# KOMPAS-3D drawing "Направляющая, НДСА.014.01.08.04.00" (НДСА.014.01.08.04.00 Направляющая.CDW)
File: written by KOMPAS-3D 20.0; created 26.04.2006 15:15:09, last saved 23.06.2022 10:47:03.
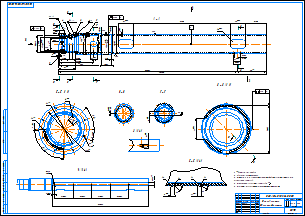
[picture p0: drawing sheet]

Sheet 1: A1, landscape

Document properties: Автор: Устинов А.В.; Организация: Эсто-вакуум; Полное имя файла: НДСА.014.01.08.04.00 Направляющая.a3d; 245497770678: <item xmlns="http://appius.ru/pdm" xmlns:xs="http://www.w3.org/2001/XMLSchema" xmlns:xsi="http://www.w3.org/2001/XMLSchema-instance" xsi:type="item">  <element xmlns:d2p1="http://v8.1c.ru/8.1/data/enterprise/current-config" xsi:type="d2p1:CatalogRef.aps_Элемен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; PLM_CDWXDTO: <item xmlns="http://appius.ru/pdm" xmlns:xs="http://www.w3.org/2001/XMLSchema" xmlns:xsi="http://www.w3.org/2001/XMLSchema-instance" xsi:type="item">  <element xmlns:d2p1="http://v8.1c.ru/8.1/data/enterprise/current-config" xsi:type="d2p1:CatalogRef.aps_Элемен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; Масса: 36.6515

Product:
- Part/product: Направляющая  | designation НДСА.014.01.08.04.00
    Масса: 36.6515
  - Component [detail]: Труба  | designation НДСА.014.01.08.04.04  | Материал: Труба$d140х10 ГОСТ 8732-78;20 ГОСТ 8731-74$ (density 0 kg/m3); source file: НДСА.014.01.08.04.04 Труба.m3d
  - Component [detail]: Труба  | designation НДСА.014.01.08.04.02  | Материал: Труба$d114х8 ГОСТ 8732-78;20 ГОСТ 8731-74$ (density 0 kg/m3); source file: НДСА.014.01.08.04.02 Труба.m3d
  - Component [detail]: Втулка  | designation НДСА.014.01.08.04.01  | Материал: Сталь 20 ГОСТ 1050-88 (density 0 kg/m3); source file: НДСА.014.01.08.04.01 Втулка.m3d
  - Component [detail]: Втулка обр. (направл.)  | Материал: Сталь 20 ГОСТ 1050-88 (density 7859 kg/m3); Масса: 1.41117; source file: Втулка обр. (направл.).m3d
  - Component [detail]: Труба обр. (направл.)  | Материал: Труба$d114х8 ГОСТ 8732-78;20 ГОСТ 8731-74$ (density 7859 kg/m3); Масса: 1.17039; source file: Труба обр. (направл.).m3d
  - Component [detail]: Шов сварной 3 (гидроподъем.)  | qty 2  | Масса: 0.0486432; source file: Шов сварной 3 (гидроподъем.).m3d
  - Component [detail]: Втулка  | designation НДСА.014.01.08.04.03  | Материал: Сталь 20 ГОСТ 1050-88 (density 7859 kg/m3); Масса: 0.959708; source file: НДСА.014.01.08.04.03 Втулка.m3d
  - Component [detail]: Труба обр. 2 (направл.)  | Материал: Труба$d140х10 ГОСТ 8732-78;20 ГОСТ 8731-74$ (density 7859 kg/m3); Масса: 32.9315; source file: Труба обр. 2 (направл.).m3d
  - Component [detail]: Шов сварной 4 (гидроподъем.)  | Масса: 0.0814568; source file: Шов сварной 4 (гидроподъем.).m3d

Title block, sheet 1: Наименование: Направляющая / Сборочный чертеж; Масса: 36,65; scale: 1:2,5; Количество листов документа: 1; organisation: ЭСТО; Форматы листов документа: A1; stored path: D:\WorkPDM\Устинов А.В\8b0af0dc-f3da-4f92-ad11-61854faa3fd1\УКРД.789.01.03.10.00 СБ Направляющая.cdw; Разработал: Волкова; Разработал, date: 16.01.2020

Views: Вид 1, Спереди, Разрез А-А, Местный разрез 1, Местный разрез 3, Разрез Б-Б, Вид по стрелке 8, Разрез Е-Е, Вид по стрелке 10
Referenced files in E:\НДСА.014.01.08.00.00 Гидроподъемник\: НДСА.014.01.08.04.00 Направляющая.a3d, Труба обр. 2 (направл.).m3d, Труба обр. (направл.).m3d, НДСА.014.01.08.04.03 Втулка.m3d, Втулка обр. (направл.).m3d, Шов сварной 3 (гидроподъем.).m3d, Шов сварной 4 (гидроподъем.).m3d
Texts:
  Js12
  НДСА.014.01.08.04.00
  Втулка обр. (направл.)
  Труба обр. (направл.)
  Шов сварной 3 (гидроподъем.)
  Втулка
  НДСА.014.01.08.04.03
  НДСА.014.01.08.04.03 Втулка
  Труба обр. 2 (направл.)
  Шов сварной 4 (гидроподъем.)
  НДСА.014.01.08.04.01
  НДСА.014.01.08.04.01 Втулка
  Труба
  НДСА.014.01.08.04.02
  НДСА.014.01.08.04.02 Труба
  НДСА.014.01.08.04.04
  НДСА.014.01.08.04.04 Труба
  НДСА.014.01.08.04.00 Направляющая
Dimensions and other numbers on the sheet: 2 №1; 1; 2; 3; 4; 114; 140; 120; 118; 1442; 90; 33; 98; 13; 82; 12; 1,25; 2,5; 0,016; 66±0,3; 22±0,3; 235±0,5; 50; 138; 136; 290; 148±1; 100; 675±1; 15; 0,025; 6,3; -7Н; 2 отв.; 40; 204; 48±0,2; 1238±0,5; 134; 20; 126; 8 отв.; 22 30'; 10; 7; 1055; 205±0,2; -7H; 5 отв.; 32,74; 1:2,5; 36,65; 16.01.2020

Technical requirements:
  * Размеры для справок.
  Сварка по ГОСТ 5264-80.
  Дет. поз. 1, 2, 4 допускается изготавливать одной деталью при
  соблюдении размеров.
  Неуказанная обработка размеров -  6,3 .
  Покрытие - обработать консистентной смазкой.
